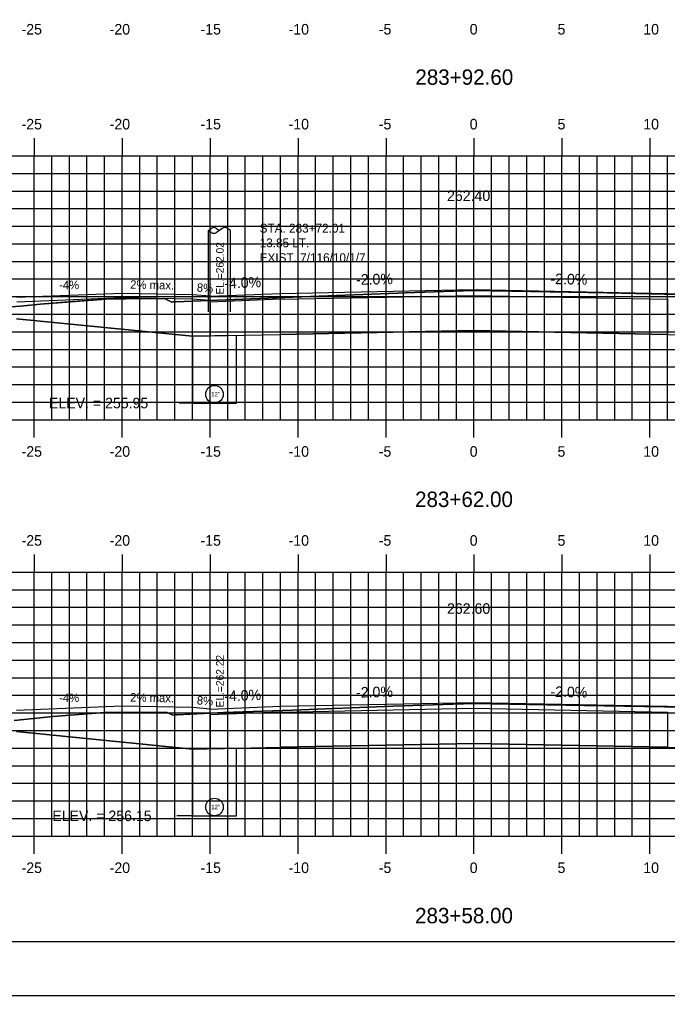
# Model space of a CAD drawing. Extents: x 856235 to 856405, y 366268 to 366378.
# Drawn here: x 856291.9 to 856328.8, y 366268.2 to 366323.6 of the extents above; entities that cross this region are included whole.
import ezdxf

# ---------------------------------------------------------------- set-up
doc = ezdxf.new("R2010")
doc.units = 0
for name, color, linetype in [('ANNOTATION', 7, 'Continuous'), ('BORDER', 7, 'Continuous'), ('D_Roadway_Centerline_Text', 7, 'Continuous'), ('D_Roadway_Drive_Gravel_LT', 7, 'Continuous'), ('D_Roadway_Drive_SubGrade', 7, 'Continuous'), ('D_Roadway_Edge_Shoulder', 7, 'Continuous'), ('D_Roadway_SubGrade', 7, 'Continuous'), ('D_Text_Monospaced', 7, 'Continuous'), ('D_Text_Standard', 7, 'Continuous'), ('H_V ANNOTATION', 7, 'Continuous'), ('JUNK COM EXC', 7, 'Continuous'), ('junk strct exc', 7, 'Continuous'), ('MAJOR', 7, 'Continuous'), ('MINOR', 7, 'Continuous'), ('PDRAIN', 7, 'Continuous'), ('PLOT BOUNDARY', 7, 'Continuous'), ('S_Roadway_Centerline', 7, 'Continuous'), ('S_Utilities_Pole_Power', 7, 'Continuous')]:
    doc.layers.add(name, color=color, linetype=linetype)

msp = doc.modelspace()

# ---------------------------------------------------------------- linework, layer by layer
at = {"layer": 'BORDER'}
msp.add_line((856242.781, 366271.236), (856402.781, 366271.236), dxfattribs=at)
at = {"layer": 'D_Roadway_Drive_Gravel_LT'}
for p, q in [((856297.781, 366308.074), (856291.781, 366307.834)), ((856301.781, 366307.994), (856297.781, 366308.074)), ((856297.791, 366307.824), (856291.791, 366307.584)), ((856301.776, 366307.744), (856297.776, 366307.824)), ((856302.781, 366307.663), (856301.761, 366307.745)), ((856302.781, 366307.914), (856301.781, 366307.994)), ((856302.781, 366307.58), (856302.781, 366307.914)), ((856297.781, 366284.614), (856291.781, 366284.374)), ((856301.781, 366284.534), (856297.781, 366284.614)), ((856302.781, 366284.454), (856301.781, 366284.534)), ((856302.781, 366284.121), (856302.781, 366284.454))]:
    msp.add_line(p, q, dxfattribs=at)
at = {"layer": 'D_Roadway_Drive_SubGrade'}
for p, q in [((856301.781, 366305.64), (856291.781, 366306.632)), ((856302.781, 366305.66), (856301.781, 366305.64)), ((856301.781, 366282.181), (856291.781, 366283.178)), ((856302.781, 366282.201), (856301.781, 366282.181))]:
    msp.add_line(p, q, dxfattribs=at)
at = {"layer": 'D_Roadway_Edge_Shoulder'}
for points in [[(856302.781, 366307.914), (856306.781, 366308.074), (856317.781, 366308.294), (856328.781, 366308.074), (856334.78, 366307.834)], [(856302.781, 366284.454), (856306.781, 366284.614), (856317.781, 366284.834), (856328.781, 366284.614), (856334.054, 366284.404)]]:
    msp.add_lwpolyline(points, dxfattribs=at)
at = {"layer": 'D_Roadway_SubGrade'}
for points in [[(856306.781, 366307.74), (856302.781, 366307.58), (856302.781, 366305.66), (856306.781, 366305.74)], [(856306.781, 366305.74), (856306.781, 366307.74), (856317.781, 366307.96), (856328.781, 366307.74), (856328.781, 366305.74), (856317.781, 366305.96)], [(856306.781, 366284.281), (856302.781, 366284.121), (856302.781, 366282.201), (856306.781, 366282.281)], [(856306.781, 366282.281), (856306.781, 366284.281), (856317.781, 366284.501), (856328.781, 366284.281), (856328.781, 366282.281), (856317.781, 366282.501)]]:
    msp.add_lwpolyline(points, close=True, dxfattribs=at)
at = {"layer": 'D_Text_Standard'}
for points in [[(856301.781, 366301.843), (856301.708, 366301.843), (856301.028, 366301.843)], [(856301.781, 366278.386), (856301.579, 366278.386), (856300.899, 366278.386)]]:
    msp.add_lwpolyline(points, dxfattribs=at)
at = {"layer": 'JUNK COM EXC'}
for points in [[(856291.781, 366306.632), (856301.781, 366305.64), (856306.781, 366305.74), (856317.781, 366305.96), (856328.781, 366305.74), (856335.78, 366305.586), (856335.781, 366308.158), (856334.63, 366308.158), (856333.411, 366308.015), (856333.315, 366308.002), (856330.64, 366308.017), (856328.588, 366308.036), (856325.349, 366308.101), (856317.731, 366308.235), (856314.412, 366308.118), (856307.504, 366307.852), (856302.732, 366307.68), (856301.781, 366307.634)], [(856301.781, 366307.634), (856300.837, 366307.587), (856300.668, 366307.591), (856300.611, 366307.582), (856300.226, 366307.769), (856299.153, 366307.782), (856296.849, 366307.753), (856294.982, 366307.606), (856293.116, 366307.459), (856291.997, 366307.346), (856288.766, 366307.134)], [(856291.781, 366283.178), (856301.781, 366282.181), (856306.781, 366282.281), (856317.781, 366282.501), (856328.781, 366282.281), (856335.054, 366282.155), (856335.038, 366284.636), (856334.033, 366284.637), (856333.255, 366284.546), (856333.193, 366284.537), (856331.485, 366284.547), (856328.602, 366284.573), (856324.051, 366284.665), (856317.749, 366284.776), (856313.162, 366284.614), (856307.467, 366284.395), (856303.535, 366284.254), (856301.781, 366284.168)], [(856301.781, 366284.168), (856300.892, 366284.124), (856300.753, 366284.127), (856300.663, 366284.113), (856300.35, 366284.265), (856296.799, 366284.263), (856293.851, 366284.031), (856291.653, 366283.81)]]:
    msp.add_lwpolyline(points, dxfattribs=at)
at = {"layer": 'junk strct exc'}
for points in [[(856301.781, 366305.64), (856301.781, 366301.843), (856304.281, 366301.843), (856304.281, 366305.69)], [(856301.781, 366282.181), (856301.781, 366278.386), (856304.281, 366278.386), (856304.281, 366282.236)]]:
    msp.add_lwpolyline(points, close=True, dxfattribs=at)
at = {"layer": 'MAJOR'}
for p, q in [((856292.781, 366316.895), (856292.781, 366315.893)), ((856297.781, 366316.895), (856297.781, 366315.893)), ((856302.781, 366316.895), (856302.781, 366315.893)), ((856307.781, 366316.895), (856307.781, 366315.893)), ((856312.781, 366316.895), (856312.781, 366315.893)), ((856317.781, 366316.895), (856317.781, 366315.893)), ((856322.781, 366316.895), (856322.781, 366315.893)), ((856327.781, 366316.895), (856327.781, 366315.893)), ((856247.781, 366315.893), (856387.781, 366315.893)), ((856247.781, 366315.893), (856387.781, 366315.893)), ((856292.781, 366300.893), (856292.781, 366315.893)), ((856297.781, 366300.893), (856297.781, 366315.893)), ((856302.781, 366300.893), (856302.781, 366315.893)), ((856307.781, 366300.893), (856307.781, 366315.893)), ((856312.781, 366300.893), (856312.781, 366315.893)), ((856317.781, 366300.893), (856317.781, 366315.893)), ((856322.781, 366300.893), (856322.781, 366315.893)), ((856327.781, 366300.893), (856327.781, 366315.893)), ((856247.781, 366310.893), (856387.781, 366310.893)), ((856247.781, 366305.893), (856387.781, 366305.893)), ((856247.781, 366300.893), (856387.781, 366300.893)), ((856247.781, 366300.893), (856387.781, 366300.893)), ((856292.781, 366299.891), (856292.781, 366300.893)), ((856297.781, 366299.891), (856297.781, 366300.893)), ((856302.781, 366299.891), (856302.781, 366300.893)), ((856307.781, 366299.891), (856307.781, 366300.893)), ((856312.781, 366299.891), (856312.781, 366300.893)), ((856317.781, 366299.891), (856317.781, 366300.893)), ((856322.781, 366299.891), (856322.781, 366300.893)), ((856327.781, 366299.891), (856327.781, 366300.893)), ((856292.781, 366293.238), (856292.781, 366292.236)), ((856297.781, 366293.238), (856297.781, 366292.236)), ((856302.781, 366293.238), (856302.781, 366292.236)), ((856307.781, 366293.238), (856307.781, 366292.236)), ((856312.781, 366293.238), (856312.781, 366292.236)), ((856317.781, 366293.238), (856317.781, 366292.236)), ((856322.781, 366293.238), (856322.781, 366292.236)), ((856327.781, 366293.238), (856327.781, 366292.236)), ((856247.781, 366292.236), (856387.781, 366292.236)), ((856247.781, 366292.236), (856387.781, 366292.236)), ((856292.781, 366277.236), (856292.781, 366292.236)), ((856297.781, 366277.236), (856297.781, 366292.236)), ((856302.781, 366277.236), (856302.781, 366292.236)), ((856307.781, 366277.236), (856307.781, 366292.236)), ((856312.781, 366277.236), (856312.781, 366292.236)), ((856317.781, 366277.236), (856317.781, 366292.236)), ((856322.781, 366277.236), (856322.781, 366292.236)), ((856327.781, 366277.236), (856327.781, 366292.236)), ((856247.781, 366287.236), (856387.781, 366287.236)), ((856247.781, 366282.236), (856387.781, 366282.236)), ((856247.781, 366277.236), (856387.781, 366277.236)), ((856247.781, 366277.236), (856387.781, 366277.236)), ((856292.781, 366276.234), (856292.781, 366277.236)), ((856297.781, 366276.234), (856297.781, 366277.236)), ((856302.781, 366276.234), (856302.781, 366277.236)), ((856307.781, 366276.234), (856307.781, 366277.236)), ((856312.781, 366276.234), (856312.781, 366277.236)), ((856317.781, 366276.234), (856317.781, 366277.236)), ((856322.781, 366276.234), (856322.781, 366277.236)), ((856327.781, 366276.234), (856327.781, 366277.236))]:
    msp.add_line(p, q, dxfattribs=at)
at = {"layer": 'MINOR'}
for p, q in [((856293.781, 366300.893), (856293.781, 366315.893)), ((856294.781, 366300.893), (856294.781, 366315.893)), ((856295.781, 366300.893), (856295.781, 366315.893)), ((856296.781, 366300.893), (856296.781, 366315.893)), ((856298.781, 366300.893), (856298.781, 366315.893)), ((856299.781, 366300.893), (856299.781, 366315.893)), ((856300.781, 366300.893), (856300.781, 366315.893)), ((856301.781, 366300.893), (856301.781, 366315.893)), ((856303.781, 366300.893), (856303.781, 366315.893)), ((856304.781, 366300.893), (856304.781, 366315.893)), ((856305.781, 366300.893), (856305.781, 366315.893)), ((856306.781, 366300.893), (856306.781, 366315.893)), ((856308.781, 366300.893), (856308.781, 366315.893)), ((856309.781, 366300.893), (856309.781, 366315.893)), ((856310.781, 366300.893), (856310.781, 366315.893)), ((856311.781, 366300.893), (856311.781, 366315.893)), ((856313.781, 366300.893), (856313.781, 366315.893)), ((856314.781, 366300.893), (856314.781, 366315.893)), ((856315.781, 366300.893), (856315.781, 366315.893)), ((856316.781, 366300.893), (856316.781, 366315.893)), ((856318.781, 366300.893), (856318.781, 366315.893)), ((856319.781, 366300.893), (856319.781, 366315.893)), ((856320.781, 366300.893), (856320.781, 366315.893)), ((856321.781, 366300.893), (856321.781, 366315.893)), ((856323.781, 366300.893), (856323.781, 366315.893)), ((856324.781, 366300.893), (856324.781, 366315.893)), ((856325.781, 366300.893), (856325.781, 366315.893)), ((856326.781, 366300.893), (856326.781, 366315.893)), ((856328.781, 366300.893), (856328.781, 366315.893)), ((856247.781, 366314.893), (856387.781, 366314.893)), ((856247.781, 366313.893), (856387.781, 366313.893)), ((856247.781, 366312.893), (856387.781, 366312.893)), ((856247.781, 366311.893), (856387.781, 366311.893)), ((856247.781, 366309.893), (856387.781, 366309.893)), ((856247.781, 366308.893), (856387.781, 366308.893)), ((856247.781, 366307.893), (856387.781, 366307.893)), ((856247.781, 366306.893), (856387.781, 366306.893)), ((856247.781, 366304.893), (856387.781, 366304.893)), ((856247.781, 366303.893), (856387.781, 366303.893)), ((856247.781, 366302.893), (856387.781, 366302.893)), ((856247.781, 366301.893), (856387.781, 366301.893)), ((856293.781, 366277.236), (856293.781, 366292.236)), ((856294.781, 366277.236), (856294.781, 366292.236)), ((856295.781, 366277.236), (856295.781, 366292.236)), ((856296.781, 366277.236), (856296.781, 366292.236)), ((856298.781, 366277.236), (856298.781, 366292.236)), ((856299.781, 366277.236), (856299.781, 366292.236)), ((856300.781, 366277.236), (856300.781, 366292.236)), ((856301.781, 366277.236), (856301.781, 366292.236)), ((856303.781, 366277.236), (856303.781, 366292.236)), ((856304.781, 366277.236), (856304.781, 366292.236)), ((856305.781, 366277.236), (856305.781, 366292.236)), ((856306.781, 366277.236), (856306.781, 366292.236)), ((856308.781, 366277.236), (856308.781, 366292.236)), ((856309.781, 366277.236), (856309.781, 366292.236)), ((856310.781, 366277.236), (856310.781, 366292.236)), ((856311.781, 366277.236), (856311.781, 366292.236)), ((856313.781, 366277.236), (856313.781, 366292.236)), ((856314.781, 366277.236), (856314.781, 366292.236)), ((856315.781, 366277.236), (856315.781, 366292.236)), ((856316.781, 366277.236), (856316.781, 366292.236)), ((856318.781, 366277.236), (856318.781, 366292.236)), ((856319.781, 366277.236), (856319.781, 366292.236)), ((856320.781, 366277.236), (856320.781, 366292.236)), ((856321.781, 366277.236), (856321.781, 366292.236)), ((856323.781, 366277.236), (856323.781, 366292.236)), ((856324.781, 366277.236), (856324.781, 366292.236)), ((856325.781, 366277.236), (856325.781, 366292.236)), ((856326.781, 366277.236), (856326.781, 366292.236)), ((856247.781, 366291.236), (856387.781, 366291.236)), ((856247.781, 366290.236), (856387.781, 366290.236)), ((856247.781, 366289.236), (856387.781, 366289.236)), ((856247.781, 366288.236), (856387.781, 366288.236)), ((856247.781, 366286.236), (856387.781, 366286.236)), ((856247.781, 366285.236), (856387.781, 366285.236)), ((856247.781, 366284.236), (856387.781, 366284.236)), ((856247.781, 366283.236), (856387.781, 366283.236)), ((856247.781, 366281.236), (856387.781, 366281.236)), ((856247.781, 366280.236), (856387.781, 366280.236)), ((856247.781, 366279.236), (856387.781, 366279.236)), ((856247.781, 366278.236), (856387.781, 366278.236))]:
    msp.add_line(p, q, dxfattribs=at)
at = {"layer": 'PDRAIN'}
for points in [[(856301.781, 366305.64), (856301.781, 366301.843), (856304.281, 366301.843), (856304.281, 366305.69)], [(856301.781, 366282.181), (856301.781, 366278.386), (856304.281, 366278.386), (856304.281, 366282.231)]]:
    msp.add_lwpolyline(points, dxfattribs=at)
for centre in [(856303.031, 366302.343), (856303.031, 366278.886)]:
    msp.add_circle(centre, 0.5, dxfattribs=at)
at = {"layer": 'PLOT BOUNDARY'}
msp.add_lwpolyline([(856234.688, 366268.177), (856404.688, 366268.177), (856404.688, 366378.177), (856234.688, 366378.177)], close=True, dxfattribs=at)
at = {"layer": 'S_Roadway_Centerline'}
for points in [[(856288.766, 366307.134), (856291.997, 366307.346), (856293.116, 366307.459), (856296.849, 366307.753), (856299.153, 366307.782), (856300.226, 366307.769), (856300.611, 366307.582), (856300.668, 366307.591), (856300.837, 366307.587), (856302.732, 366307.68), (856307.504, 366307.852), (856314.412, 366308.118), (856317.731, 366308.235), (856325.349, 366308.101), (856328.588, 366308.036), (856330.64, 366308.017), (856333.315, 366308.002), (856333.411, 366308.015), (856334.63, 366308.158), (856336.902, 366308.157), (856341.841, 366308.513), (856353.214, 366308.843), (856361.49, 366308.945)], [(856291.653, 366283.81), (856293.851, 366284.031), (856296.799, 366284.263), (856298.619, 366284.286), (856300.35, 366284.265), (856300.663, 366284.113), (856300.753, 366284.127), (856300.892, 366284.124), (856303.535, 366284.254), (856307.467, 366284.395), (856313.162, 366284.614), (856317.749, 366284.776), (856324.051, 366284.665), (856328.602, 366284.573), (856331.485, 366284.547), (856333.193, 366284.537), (856333.255, 366284.546), (856334.033, 366284.637), (856337.4, 366284.635), (856340.331, 366284.846), (856357.003, 366285.329), (856361.802, 366285.388)]]:
    msp.add_lwpolyline(points, dxfattribs=at)
at = {"layer": 'S_Utilities_Pole_Power'}
for p, q in [((856302.683, 366311.651), (856302.839, 366311.761)), ((856302.683, 366307.031), (856302.686, 366311.651)), ((856302.839, 366311.54), (856302.683, 366311.651)), ((856303.151, 366311.761), (856303.308, 366311.651)), ((856303.308, 366311.651), (856303.151, 366311.54)), ((856303.464, 366311.761), (856303.308, 366311.651)), ((856303.933, 366311.651), (856303.777, 366311.761)), ((856303.933, 366307.031), (856303.936, 366311.651))]:
    msp.add_line(p, q, dxfattribs=at)
for centre, start, end in [((856302.995, 366311.54), 90, 125.2644), ((856302.995, 366311.761), 234.7356, 270), ((856302.995, 366311.54), 54.7356, 90), ((856302.995, 366311.761), 270, 305.2644), ((856303.62, 366311.54), 90, 125.2644), ((856303.62, 366311.54), 54.7356, 90)]:
    msp.add_arc(centre, 0.271, start, end, dxfattribs=at)

# ---------------------------------------------------------------- texts
at = {"layer": 'ANNOTATION'}
for s, rotation, p in [('-2.0%', 1.1458, (856311.084, 366308.56)), ('-2.0%', 358.8542, (856322.124, 366308.607)), ('-4.0%', 2.2906, (856303.597, 366308.347)), ('-4.0%', 2.2906, (856303.597, 366284.888)), ('-2.0%', 1.1458, (856311.084, 366285.101)), ('-2.0%', 358.8542, (856322.124, 366285.148))]:
    msp.add_text(s, height=0.6, rotation=rotation, dxfattribs=at).set_placement(p)
at = {"layer": 'D_Roadway_Centerline_Text'}
for s, p in [('262.40', (856316.25, 366313.326)), ('262.60', (856316.25, 366289.866))]:
    msp.add_text(s, height=0.6, dxfattribs=at).set_placement(p)
at = {"layer": 'D_Roadway_Drive_Gravel_LT'}
for p in [(856294.199, 366308.314), (856294.199, 366284.854)]:
    msp.add_text('-4%', height=0.48, dxfattribs=at).set_placement(p)
for s, rotation, p in [('2% max.', 358.8078, (856298.234, 366308.344)), ('8%', 355.4261, (856302.012, 366308.181)), ('2% max.', 358.8078, (856298.234, 366284.884)), ('8%', 355.4261, (856302.012, 366284.721))]:
    msp.add_text(s, height=0.48, rotation=rotation, dxfattribs=at).set_placement(p)
at = {"layer": 'D_Text_Monospaced'}
for s, height, p in [('STA. 283+72.01', 0.49998, (856305.599, 366311.529)), ('13.85 LT.', 0.5, (856305.599, 366310.695)), ('EXIST. 7/116/10/1/7', 0.49998, (856305.599, 366309.855))]:
    msp.add_text(s, height=height, dxfattribs=at).set_placement(p)
at = {"layer": 'D_Text_Standard'}
for s, p in [(' EL.=262.02', (856303.555, 366307.848)), (' EL.=262.22', (856303.555, 366284.389))]:
    msp.add_text(s, height=0.4335, rotation=90, dxfattribs=at).set_placement(p)
for s, p in [('ELEV. = 255.95', (856293.623, 366301.543)), ('ELEV. = 256.15', (856293.815, 366278.086))]:
    msp.add_text(s, height=0.6, dxfattribs=at).set_placement(p)
at = {"layer": 'H_V ANNOTATION'}
for s, height, p in [('-25', 0.6, (856292.066, 366322.785)), ('-20', 0.6, (856297.074, 366322.785)), ('-15', 0.6, (856302.238, 366322.785)), ('-10', 0.6, (856307.246, 366322.785)), ('-5', 0.6, (856312.371, 366322.785)), ('0', 0.6, (856317.54, 366322.785)), ('5', 0.6, (856322.532, 366322.785)), ('10', 0.6, (856327.406, 366322.785)), ('283+92.60', 0.875, (856314.449, 366319.928)), ('-25', 0.6, (856292.066, 366317.393)), ('-20', 0.6, (856297.074, 366317.393)), ('-10', 0.6, (856307.246, 366317.393)), ('0', 0.6, (856317.54, 366317.393)), ('10', 0.6, (856327.406, 366317.393)), ('-15', 0.6, (856302.238, 366317.393)), ('-5', 0.6, (856312.371, 366317.393)), ('5', 0.6, (856322.532, 366317.393)), ('-25', 0.6, (856292.066, 366298.793)), ('-20', 0.6, (856297.074, 366298.793)), ('-15', 0.6, (856302.238, 366298.793)), ('-10', 0.6, (856307.246, 366298.793)), ('-5', 0.6, (856312.371, 366298.793)), ('0', 0.6, (856317.54, 366298.793)), ('5', 0.6, (856322.532, 366298.793)), ('10', 0.6, (856327.406, 366298.793)), ('283+62.00', 0.875, (856314.433, 366295.936)), ('-25', 0.6, (856292.066, 366293.736)), ('-20', 0.6, (856297.074, 366293.736)), ('-15', 0.6, (856302.238, 366293.736)), ('-10', 0.6, (856307.246, 366293.736)), ('-5', 0.6, (856312.371, 366293.736)), ('0', 0.6, (856317.54, 366293.736)), ('5', 0.6, (856322.532, 366293.736)), ('10', 0.6, (856327.406, 366293.736)), ('-25', 0.6, (856292.066, 366275.136)), ('-20', 0.6, (856297.074, 366275.136)), ('-15', 0.6, (856302.238, 366275.136)), ('-10', 0.6, (856307.246, 366275.136)), ('-5', 0.6, (856312.371, 366275.136)), ('0', 0.6, (856317.54, 366275.136)), ('5', 0.6, (856322.532, 366275.136)), ('10', 0.6, (856327.406, 366275.136)), ('283+58.00', 0.875, (856314.433, 366272.28))]:
    msp.add_text(s, height=height, dxfattribs=at).set_placement(p)
at = {"layer": 'PDRAIN'}
for p in [(856302.84, 366302.218), (856302.84, 366278.762)]:
    msp.add_text('12"', height=0.25, dxfattribs=at).set_placement(p)
at = {"layer": 'S_Roadway_Centerline'}
for s, p in [('L', (856317.723, 366308.228)), ('C', (856317.726, 366308.235)), ('L', (856317.74, 366284.769)), ('C', (856317.743, 366284.776))]:
    msp.add_text(s, height=0.0146, dxfattribs=at).set_placement(p)

doc.saveas('drawing.dxf')
